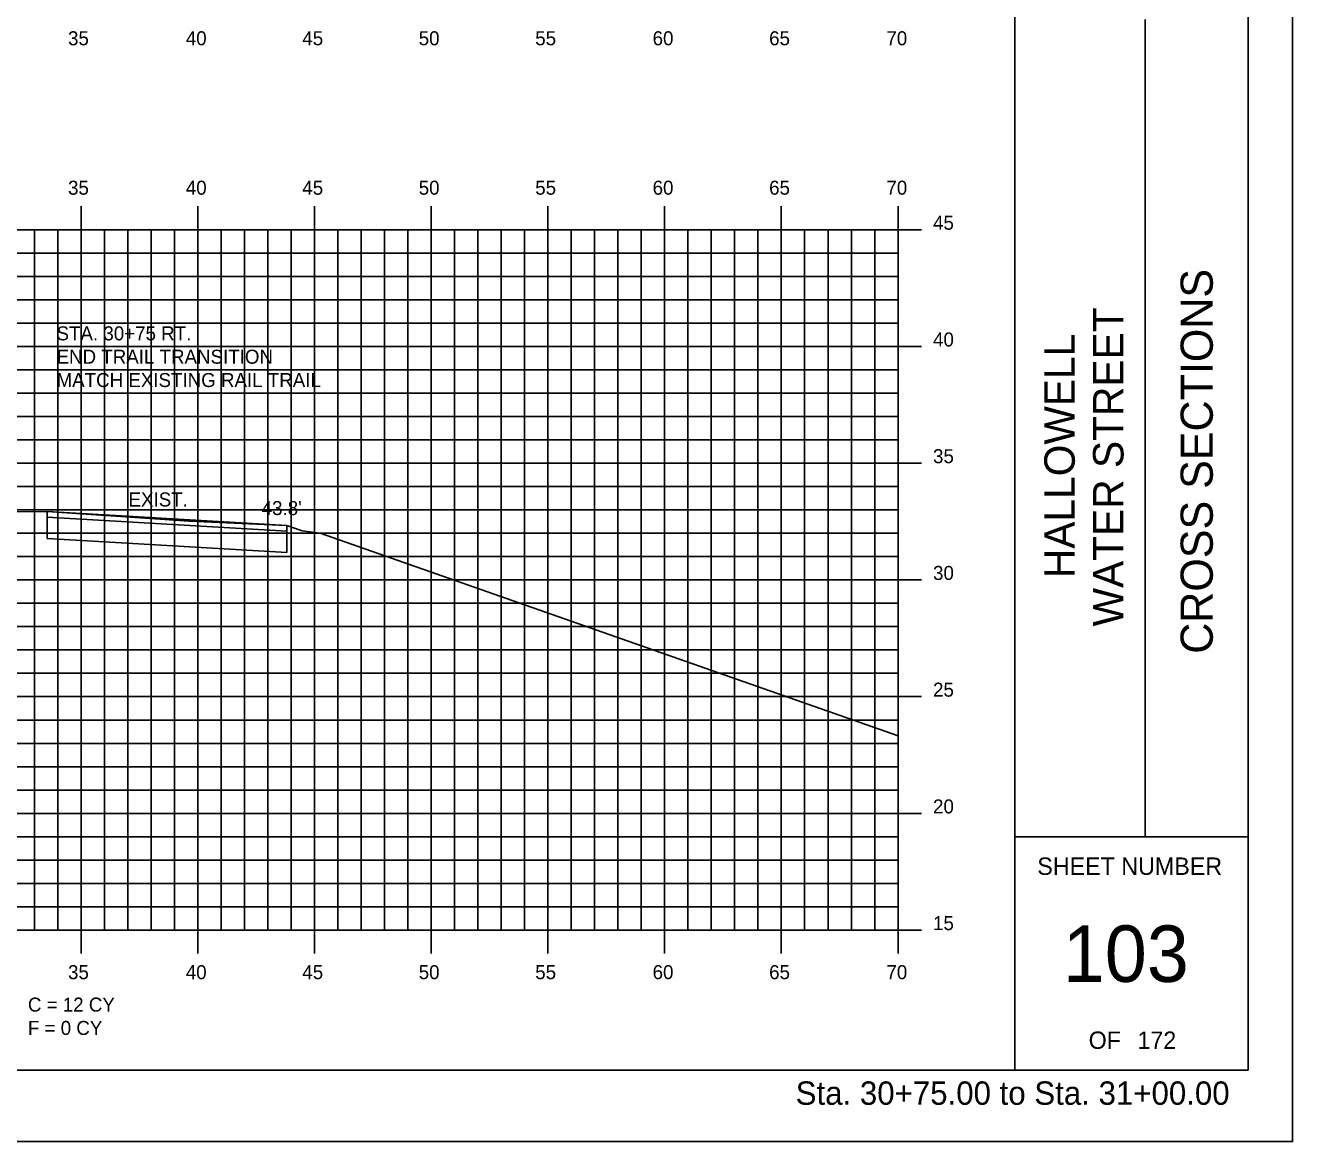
# Model space of a CAD drawing. Extents: x 1037709 to 1037879, y 394883 to 394993.
# Drawn here: x 1037824.8 to 1037879.1, y 394882.6 to 394930.4 of the extents above; entities that cross this region are included whole.
import ezdxf

# ---------------------------------------------------------------- set-up
doc = ezdxf.new("R2010")
doc.units = 0
for name, color, linetype in [('ANNOTATION', 7, 'Continuous'), ('BORDER', 7, 'Continuous'), ('D_Roadway_FinishedGrade', 7, 'Continuous'), ('D_Text_Standard', 7, 'Continuous'), ('H_V ANNOTATION', 7, 'Continuous'), ('HIGHWAY_TITLE', 7, 'Continuous'), ('MAJOR', 7, 'Continuous'), ('MINOR', 7, 'Continuous'), ('PLOT BOUNDARY', 7, 'Continuous'), ('S_Roadway_Centerline', 7, 'Continuous')]:
    doc.layers.add(name, color=color, linetype=linetype)

msp = doc.modelspace()

# ---------------------------------------------------------------- linework, layer by layer
at = {"layer": 'BORDER'}
for p, q in [((1037867.157, 394885.686), (1037867.157, 394990.689)), ((1037877.157, 394885.686), (1037877.157, 394990.686)), ((1037872.748, 394895.689), (1037872.748, 394930.689)), ((1037867.157, 394895.689), (1037877.157, 394895.689)), ((1037717.157, 394885.686), (1037877.157, 394885.686))]:
    msp.add_line(p, q, dxfattribs=at)
at = {"layer": 'D_Roadway_FinishedGrade'}
for p, q in [((1037825.706, 394908.455), (1037825.706, 394909.621)), ((1037825.706, 394909.621), (1037835.977, 394909.02)), ((1037825.706, 394909.374), (1037835.977, 394908.773)), ((1037835.977, 394907.854), (1037835.977, 394909.02)), ((1037825.706, 394908.455), (1037835.977, 394907.854))]:
    msp.add_line(p, q, dxfattribs=at)
at = {"layer": 'MAJOR'}
for p, q in [((1037827.157, 394922.688), (1037827.157, 394921.686)), ((1037832.157, 394922.688), (1037832.157, 394921.686)), ((1037837.157, 394922.688), (1037837.157, 394921.686)), ((1037842.157, 394922.688), (1037842.157, 394921.686)), ((1037847.157, 394922.688), (1037847.157, 394921.686)), ((1037852.157, 394922.688), (1037852.157, 394921.686)), ((1037857.157, 394922.688), (1037857.157, 394921.686)), ((1037862.157, 394922.688), (1037862.157, 394921.686)), ((1037722.157, 394921.686), (1037862.157, 394921.686)), ((1037827.157, 394891.686), (1037827.157, 394921.686)), ((1037832.157, 394891.686), (1037832.157, 394921.686)), ((1037837.157, 394891.686), (1037837.157, 394921.686)), ((1037842.157, 394891.686), (1037842.157, 394921.686)), ((1037847.157, 394891.686), (1037847.157, 394921.686)), ((1037852.157, 394891.686), (1037852.157, 394921.686)), ((1037857.157, 394891.686), (1037857.157, 394921.686)), ((1037863.159, 394921.686), (1037861.155, 394921.686)), ((1037862.157, 394891.686), (1037862.157, 394921.686)), ((1037722.157, 394916.686), (1037862.157, 394916.686)), ((1037863.159, 394916.686), (1037861.155, 394916.686)), ((1037722.157, 394911.686), (1037862.157, 394911.686)), ((1037863.159, 394911.686), (1037861.155, 394911.686)), ((1037722.157, 394906.686), (1037862.157, 394906.686)), ((1037863.159, 394906.686), (1037861.155, 394906.686)), ((1037722.157, 394901.686), (1037862.157, 394901.686)), ((1037863.159, 394901.686), (1037861.155, 394901.686)), ((1037722.157, 394896.686), (1037862.157, 394896.686)), ((1037863.159, 394896.686), (1037861.155, 394896.686)), ((1037722.157, 394891.686), (1037862.157, 394891.686)), ((1037827.157, 394890.684), (1037827.157, 394891.686)), ((1037832.157, 394890.684), (1037832.157, 394891.686)), ((1037837.157, 394890.684), (1037837.157, 394891.686)), ((1037842.157, 394890.684), (1037842.157, 394891.686)), ((1037847.157, 394890.684), (1037847.157, 394891.686)), ((1037852.157, 394890.684), (1037852.157, 394891.686)), ((1037857.157, 394890.684), (1037857.157, 394891.686)), ((1037863.159, 394891.686), (1037861.155, 394891.686)), ((1037862.157, 394890.684), (1037862.157, 394891.686))]:
    msp.add_line(p, q, dxfattribs=at)
at = {"layer": 'MINOR'}
for p, q in [((1037825.157, 394891.686), (1037825.157, 394921.686)), ((1037826.157, 394891.686), (1037826.157, 394921.686)), ((1037828.157, 394891.686), (1037828.157, 394921.686)), ((1037829.157, 394891.686), (1037829.157, 394921.686)), ((1037830.157, 394891.686), (1037830.157, 394921.686)), ((1037831.157, 394891.686), (1037831.157, 394921.686)), ((1037833.157, 394891.686), (1037833.157, 394921.686)), ((1037834.157, 394891.686), (1037834.157, 394921.686)), ((1037835.157, 394891.686), (1037835.157, 394921.686)), ((1037836.157, 394891.686), (1037836.157, 394921.686)), ((1037838.157, 394891.686), (1037838.157, 394921.686)), ((1037839.157, 394891.686), (1037839.157, 394921.686)), ((1037840.157, 394891.686), (1037840.157, 394921.686)), ((1037841.157, 394891.686), (1037841.157, 394921.686)), ((1037843.157, 394891.686), (1037843.157, 394921.686)), ((1037844.157, 394891.686), (1037844.157, 394921.686)), ((1037845.157, 394891.686), (1037845.157, 394921.686)), ((1037846.157, 394891.686), (1037846.157, 394921.686)), ((1037848.157, 394891.686), (1037848.157, 394921.686)), ((1037849.157, 394891.686), (1037849.157, 394921.686)), ((1037850.157, 394891.686), (1037850.157, 394921.686)), ((1037851.157, 394891.686), (1037851.157, 394921.686)), ((1037853.157, 394891.686), (1037853.157, 394921.686)), ((1037854.157, 394891.686), (1037854.157, 394921.686)), ((1037855.157, 394891.686), (1037855.157, 394921.686)), ((1037856.157, 394891.686), (1037856.157, 394921.686)), ((1037858.157, 394891.686), (1037858.157, 394921.686)), ((1037859.157, 394891.686), (1037859.157, 394921.686)), ((1037860.157, 394891.686), (1037860.157, 394921.686)), ((1037861.157, 394891.686), (1037861.157, 394921.686)), ((1037722.157, 394920.686), (1037862.157, 394920.686)), ((1037862.157, 394920.686), (1037861.155, 394920.686)), ((1037722.157, 394919.686), (1037862.157, 394919.686)), ((1037862.157, 394919.686), (1037861.155, 394919.686)), ((1037722.157, 394918.686), (1037862.157, 394918.686)), ((1037862.157, 394918.686), (1037861.155, 394918.686)), ((1037722.157, 394917.686), (1037862.157, 394917.686)), ((1037862.157, 394917.686), (1037861.155, 394917.686)), ((1037722.157, 394915.686), (1037862.157, 394915.686)), ((1037862.157, 394915.686), (1037861.155, 394915.686)), ((1037722.157, 394914.686), (1037862.157, 394914.686)), ((1037862.157, 394914.686), (1037861.155, 394914.686)), ((1037722.157, 394913.686), (1037862.157, 394913.686)), ((1037862.157, 394913.686), (1037861.155, 394913.686)), ((1037722.157, 394912.686), (1037862.157, 394912.686)), ((1037862.157, 394912.686), (1037861.155, 394912.686)), ((1037722.157, 394910.686), (1037862.157, 394910.686)), ((1037862.157, 394910.686), (1037861.155, 394910.686)), ((1037722.157, 394909.686), (1037862.157, 394909.686)), ((1037862.157, 394909.686), (1037861.155, 394909.686)), ((1037722.157, 394908.686), (1037862.157, 394908.686)), ((1037862.157, 394908.686), (1037861.155, 394908.686)), ((1037722.157, 394907.686), (1037862.157, 394907.686)), ((1037862.157, 394907.686), (1037861.155, 394907.686)), ((1037722.157, 394905.686), (1037862.157, 394905.686)), ((1037862.157, 394905.686), (1037861.155, 394905.686)), ((1037722.157, 394904.686), (1037862.157, 394904.686)), ((1037862.157, 394904.686), (1037861.155, 394904.686)), ((1037722.157, 394903.686), (1037862.157, 394903.686)), ((1037862.157, 394903.686), (1037861.155, 394903.686)), ((1037722.157, 394902.686), (1037862.157, 394902.686)), ((1037862.157, 394902.686), (1037861.155, 394902.686)), ((1037722.157, 394900.686), (1037862.157, 394900.686)), ((1037862.157, 394900.686), (1037861.155, 394900.686)), ((1037722.157, 394899.686), (1037862.157, 394899.686)), ((1037862.157, 394899.686), (1037861.155, 394899.686)), ((1037722.157, 394898.686), (1037862.157, 394898.686)), ((1037862.157, 394898.686), (1037861.155, 394898.686)), ((1037722.157, 394897.686), (1037862.157, 394897.686)), ((1037862.157, 394897.686), (1037861.155, 394897.686)), ((1037722.157, 394895.686), (1037862.157, 394895.686)), ((1037862.157, 394895.686), (1037861.155, 394895.686)), ((1037722.157, 394894.686), (1037862.157, 394894.686)), ((1037862.157, 394894.686), (1037861.155, 394894.686)), ((1037722.157, 394893.686), (1037862.157, 394893.686)), ((1037862.157, 394893.686), (1037861.155, 394893.686)), ((1037722.157, 394892.686), (1037862.157, 394892.686)), ((1037862.157, 394892.686), (1037861.155, 394892.686))]:
    msp.add_line(p, q, dxfattribs=at)
at = {"layer": 'PLOT BOUNDARY'}
msp.add_lwpolyline([(1037709.064, 394882.627), (1037879.064, 394882.627), (1037879.064, 394992.627), (1037709.064, 394992.627)], close=True, dxfattribs=at)
at = {"layer": 'S_Roadway_Centerline'}
msp.add_lwpolyline([(1037823.625, 394909.598), (1037825.706, 394909.621), (1037831.79, 394909.201), (1037835.977, 394909.02), (1037836.629, 394908.789), (1037837.398, 394908.683), (1037862.157, 394900.002)], dxfattribs=at)

# ---------------------------------------------------------------- texts
at = {"layer": 'ANNOTATION'}
for s, p in [('STA. 30+75 RT.', (1037826.106, 394916.947)), ('END TRAIL TRANSITION', (1037826.106, 394915.947)), ('MATCH EXISTING RAIL TRAIL', (1037826.106, 394914.947)), ('C = 12 CY', (1037824.879, 394888.197)), ('F = 0 CY', (1037824.879, 394887.197))]:
    msp.add_text(s, height=0.6, dxfattribs=at).set_placement(p)
at = {"layer": 'BORDER'}
msp.add_text('CROSS SECTIONS', height=1.37787, rotation=90, dxfattribs=at).set_placement((1037875.642, 394903.523))
for s, height, p in [('SHEET NUMBER', 0.74527, (1037868.123, 394894.052)), ('103', 2.4194, (1037869.217, 394889.468)), ('OF', 0.7453, (1037870.324, 394886.599)), ('172', 0.7453, (1037872.414, 394886.599))]:
    msp.add_text(s, height=height, dxfattribs=at).set_placement(p)
at = {"layer": 'D_Text_Standard'}
for s, p in [('EXIST.', (1037829.19, 394909.831)), ("43.8'", (1037834.894, 394909.464))]:
    msp.add_text(s, height=0.6, dxfattribs=at).set_placement(p)
at = {"layer": 'H_V ANNOTATION'}
for s, height, p in [('35', 0.6, (1037826.598, 394929.586)), ('40', 0.6, (1037831.643, 394929.586)), ('45', 0.6, (1037836.635, 394929.586)), ('50', 0.6, (1037841.622, 394929.586)), ('55', 0.6, (1037846.614, 394929.586)), ('60', 0.6, (1037851.643, 394929.586)), ('65', 0.6, (1037856.635, 394929.586)), ('70', 0.6, (1037861.659, 394929.586)), ('35', 0.6, (1037826.598, 394923.186)), ('40', 0.6, (1037831.643, 394923.186)), ('45', 0.6, (1037836.635, 394923.186)), ('50', 0.6, (1037841.622, 394923.186)), ('55', 0.6, (1037846.614, 394923.186)), ('60', 0.6, (1037851.643, 394923.186)), ('65', 0.6, (1037856.635, 394923.186)), ('70', 0.6, (1037861.659, 394923.186)), ('45', 0.6, (1037863.657, 394921.686)), ('40', 0.6, (1037863.657, 394916.686)), ('35', 0.6, (1037863.657, 394911.686)), ('30', 0.6, (1037863.657, 394906.686)), ('25', 0.6, (1037863.657, 394901.686)), ('20', 0.6, (1037863.657, 394896.686)), ('15', 0.6, (1037863.657, 394891.686)), ('35', 0.6, (1037826.598, 394889.586)), ('40', 0.6, (1037831.643, 394889.586)), ('45', 0.6, (1037836.635, 394889.586)), ('50', 0.6, (1037841.622, 394889.586)), ('55', 0.6, (1037846.614, 394889.586)), ('60', 0.6, (1037851.643, 394889.586)), ('65', 0.6, (1037856.635, 394889.586)), ('70', 0.6, (1037861.659, 394889.586)), ('Sta. 30+75.00 to Sta. 31+00.00', 1.0002, (1037857.772, 394884.206))]:
    msp.add_text(s, height=height, dxfattribs=at).set_placement(p)
at = {"layer": 'HIGHWAY_TITLE'}
for s, height, p in [('WATER STREET', 1.30428, (1037871.816, 394904.696)), ('HALLOWELL', 1.3043, (1037869.729, 394906.763))]:
    msp.add_text(s, height=height, rotation=90, dxfattribs=at).set_placement(p)

doc.saveas('drawing.dxf')
